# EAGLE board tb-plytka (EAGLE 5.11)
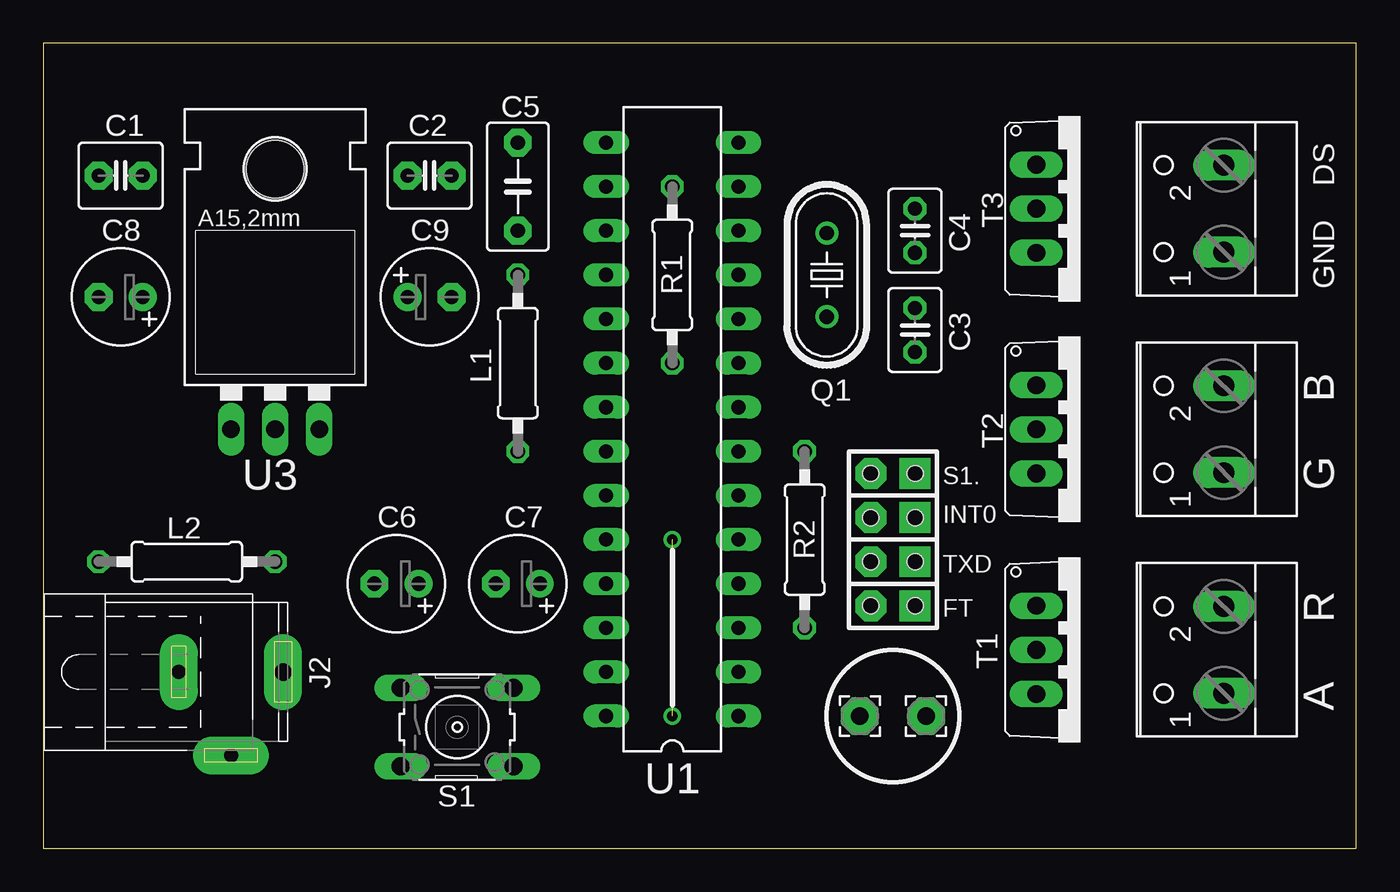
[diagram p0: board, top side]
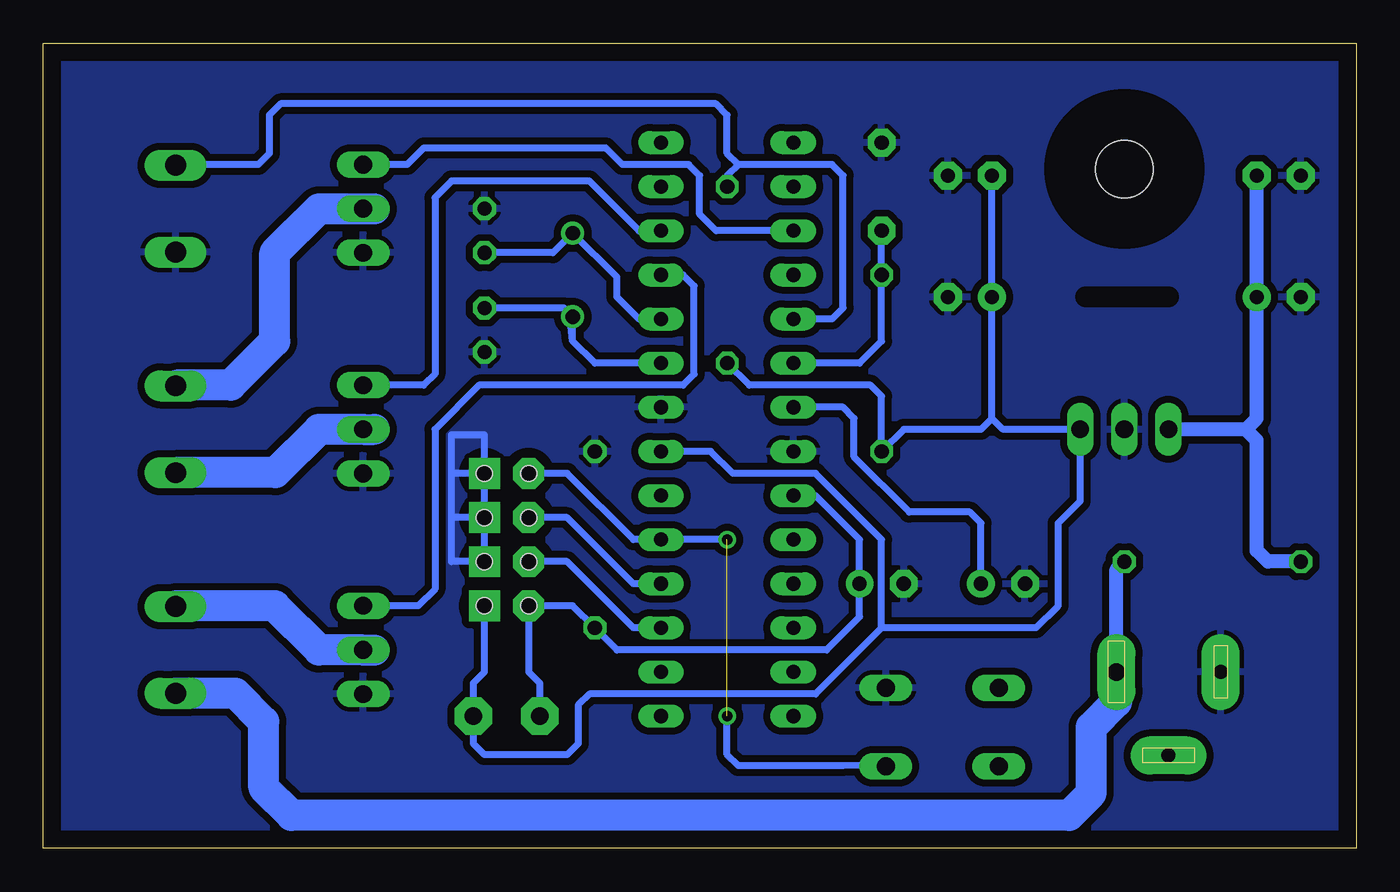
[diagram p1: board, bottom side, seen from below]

Size 75.55 x 46.34 mm. Coordinates in mm from the lower left corner, seen from the top.
Outline: 0,0 75.55,0 75.55,46.34 0,46.34 0,0
Copper layers (1*16): Top 0.035mm / dielectric 1.5mm / Bottom 0.035mm
Design rules "default": minimum track width 10mil, minimum drill 24mil, track to track 8mil, track to pad 8mil, pad to pad 8mil, via to via 8mil, smd to smd 8mil, copper to edge 40mil, drill to drill 8mil, minimum pad ring 10mil, minimum via ring 8mil, stop-mask expansion 4mil, vias tented up to drill 0mil, thermal gap 10mil
Holes 0.9 mm at 47.62,21.59 50.17,21.59 47.62,19.05 50.17,19.05 47.62,16.51 50.17,16.51 47.62,13.97 50.17,13.97
bRestrict: 1 lines

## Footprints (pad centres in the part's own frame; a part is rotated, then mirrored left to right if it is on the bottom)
C2.5-4 = drill 0.813 pad 1.6 octagon: 1 -1.27,0; 2 1.27,0
C025-030X050 = drill 0.813 octagon: 1 -1.27,0; 2 1.27,0
C5B3.5 = drill 0.813 pad 1.6 octagon: 1 -2.54,0; 2 2.54,0
E2,5-6 = drill 0.813 pad 1.6 round: + -1.27,0 | drill 0.813 pad 1.6 octagon: - 1.27,0
SIP-100-02-32 = drill 0.813 pad 1.778 square: 1 -1.27,0 | drill 0.813 pad 1.778 octagon: 2 1.27,0
SPC4077 = drill 0.8 pad 2.184 long: 1 -3,0; 2 0,-4.8 | drill 1 pad 2.184 long: 3 3,0
0207/10 = drill 0.813 octagon: 1 -5.08,0; 2 5.08,0
2,15/1,0 = drill 1.016 pad 2.159 octagon: 1 0,0
HC49U-V = drill 0.813 round: 1 -2.413,0; 2 2.413,0
B3F-10XX = drill 1.016 long: 1 -3.251,2.261; 2 3.251,2.261; 3 -3.251,-2.261; 4 3.251,-2.261
TO220V = drill 1.016 long: 1 -2.54,-2.54; 2 0,-2.54; 3 2.54,-2.54
DIL28-3 = drill 0.813 long: 1 -16.51,-3.81; 2 -13.97,-3.81; 3 -11.43,-3.81; 4 -8.89,-3.81; 5 -6.35,-3.81; 6 -3.81,-3.81; 7 -1.27,-3.81; 8 1.27,-3.81; 9 3.81,-3.81; 10 6.35,-3.81; 11 8.89,-3.81; 12 11.43,-3.81; 13 13.97,-3.81; 14 16.51,-3.81; 15 16.51,3.81; 16 13.97,3.81; 17 11.43,3.81; 18 8.89,3.81; 19 6.35,3.81; 20 3.81,3.81; 21 1.27,3.81; 22 -1.27,3.81; 23 -3.81,3.81; 24 -6.35,3.81; 25 -8.89,3.81; 26 -11.43,3.81; 27 -13.97,3.81; 28 -16.51,3.81
78XXL = drill 1.016 long: GND 0,-3.81; IN -2.54,-3.81; OUT 2.54,-3.81 | hole 3.302: 0,11.176
W237-102 = drill 1.194 long: 1 -2.5,-1.27; 2 2.5,-1.27

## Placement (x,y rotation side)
C1  100nF  [C2.5-4]  4.45,38.73 180 top
C2  100nF  [C2.5-4]  22.22,38.73 0 top
C3  22pF  [C025-030X050]  50.17,29.84 90 top
C4  22pF  [C025-030X050]  50.17,35.56 270 top
C5  100nF  [C5B3.5]  27.3,38.1 90 top
C6  1uF  [E2,5-6]  20.32,15.24 180 top
C7  47uF  [E2,5-6]  27.3,15.24 180 top
C8  220uF  [E2,5-6]  4.45,31.75 180 top
C9  100uF  [E2,5-6]  22.22,31.75 0 top
FT  2PJ  [SIP-100-02-32]  48.9,13.97 180 top
INT0  2PJ  [SIP-100-02-32]  48.9,19.05 180 top
J2  [SPC4077]  10.8,10.16 0 top
L1  10uH  [0207/10]  27.3,27.94 90 top
L2  10uH  [0207/10]  8.25,16.51 180 top
PAD5  [2,15/1,0]  50.8,7.62 270 top
PAD6  [2,15/1,0]  46.99,7.62 270 top
Q1  11,052MHz  [HC49U-V]  45.09,33.02 270 top
R1  4.7k  [0207/10]  36.2,33.02 270 top
R2  10k  [0207/10]  43.82,17.78 270 top
S1  [B3F-10XX]  23.81,6.99 0 top
S1.  2PJ  [SIP-100-02-32]  48.9,21.59 180 top
T1  BUZ11  [TO220V]  59.69,11.43 270 top
T2  BUZ11  [TO220V]  59.69,24.13 270 top
T3  BUZ11  [TO220V]  59.69,36.83 270 top
TXD  2PJ  [SIP-100-02-32]  48.9,16.51 180 top
U1  ATMEGA88-PU  [DIL28-3]  36.2,24.13 90 top
U3  7805  [78XXL]  13.34,27.94 0 top
X1  [W237-102]  66.67,11.43 90 top
X3  [W237-102]  66.67,24.13 90 top
X4  [W237-102]  66.67,36.83 90 top

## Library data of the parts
C1 C2 C5 = capacitor-wima
C3 C4 C6-C9 = rcl
FT INT0 S1. TXD = con-headers-jp
J2 = con-jack; OC_FARNELL: unknown; OC_NEWARK: unknown
L1 L2 R1 R2 = resistor
PAD5 PAD6 = wirepad
Q1 = crystal; OC_FARNELL: 1666969; OC_NEWARK: unknown
S1 = switch-omron; MPN: B3F-1000; OC_FARNELL: 176432; OC_NEWARK: 36M3542
T1-T3 = transistor
U1 = atmega8
U3 = v-reg
X1 X3 X4 = con-wago-500; MPN: 237-102; OC_FARNELL: unknown; OC_NEWARK: 70K9898

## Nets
1W: R1.1 U1.19 X4.2
+5V: C2.1 C9.+ FT.1 L1.1 PAD5.1 R1.2 U1.7 U3.OUT
+12V: J2.3 L2.1 X1.1
GND: C1.2 C2.2 C3.1 C4.1 C5.2 C6.- C7.- C8.- C9.- INT0.1 J2.1 R2.1 S1.2 S1..1 T1.3 T2.3 T3.3 TXD.1 U1.8 U1.22 U3.GND X4.1
N$4: C5.1 L1.2 U1.20
N$5: C6.+ U1.21
N$6: C7.+ FT.2 PAD6.1 R2.2 U1.23
N$7: INT0.2 U1.4
N$8: T3.2 X3.2
N$9: T2.2 X3.1
N$10: T1.2 X1.2
N$11: C1.1 C8.+ L2.2 U3.IN
N$13: T1.1 U1.11
N$14: T2.1 U1.12
N$15: TXD.2 U1.3
N$20: C3.2 Q1.2 U1.9
N$21: C4.2 Q1.1 U1.10
N$23: S1.4 S1..2 U1.5
N$24: T3.1 U1.17

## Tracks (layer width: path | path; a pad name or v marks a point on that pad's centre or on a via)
1W
  Bottom 0.406: U1.19 30.16,30.48 29.53,31.11 29.53,38.73 30.16,39.37 35.56,39.37 | R1.1 36.2,38.73 35.56,39.37 | X4.2 67.91,39.37 63.18,39.37 62.55,40 62.55,42.23 61.91,42.86 36.83,42.86 36.2,42.23 36.2,40 35.56,39.37
+5V
  Bottom 0.406: U1.7 37.15,22.86 35.88,21.59 31.11,21.59 27.3,17.78 27.3,12.7 | C2.1 C9.+ 20.95,24.77 | 27.3,12.7 31.11,8.89 44.13,8.89 44.77,8.26 44.77,6.03 45.4,5.4 50.17,5.4 50.8,6.03 PAD5.1 50.8,9.53 50.17,10.16 FT.1 | R1.2 34.93,26.67 27.94,26.67 27.3,26.04 L1.1 26.04,24.13 21.59,24.13 20.95,24.77 | 20.95,24.77 20.32,24.13 U3.OUT 15.88,20 17.14,18.73 17.14,13.97 18.41,12.7 27.3,12.7
+12V
  Bottom 0.813: J2.3 13.79,16.05 L2.1
  Bottom 1.778: J2.3 13.79,8.43 15.24,6.99 15.24,3.18 16.51,1.9 61.28,1.9 62.87,3.49 62.87,7.3 64.49,8.93 X1.1
GND
  Bottom 0.406: INT0.1 TXD.1 52.07,16.51 52.07,19.05 | INT0.1 52.07,19.05 | INT0.1 S1..1 | S1..1 50.17,23.81 52.07,23.81 52.07,21.59 | S1..1 52.07,21.59 | 52.07,19.05 52.07,21.59
  pour Bottom (isolate 0.406): -4.45,46.99 77.79,46.99 77.79,-2.54 -4.45,-2.54
N$4
  Bottom 0.406: U1.20 28.57,27.94 27.3,29.21 L1.2 C5.1
N$5
  Bottom 0.406: U1.21 29.53,25.4 28.89,24.77 28.89,22.54 25.72,19.37 22.22,19.37 21.59,18.73 C6.+
N$6
  Bottom 0.406: U1.23 31.11,20.32 28.57,17.78 C7.+ 28.57,13.34 30.48,11.43 42.55,11.43 R2.2 45.09,13.97 FT.2 47.62,10.16 46.99,9.53 PAD6.1
N$7
  Bottom 0.406: U1.4 41.59,15.24 45.4,19.05 INT0.2
N$8
  Bottom 1.778: 56.52,36.83 T3.2 59.69,36.83 62.23,34.29 62.23,29.21 64.77,26.67 67.91,26.67 X3.2
N$9
  Bottom 1.778: 56.52,24.13 T2.2 59.69,24.13 62.19,21.63 X3.1
N$10
  Bottom 1.778: 56.52,11.43 T1.2 59.69,11.43 62.23,13.97 67.91,13.97 X1.2
N$11
  Bottom 0.406: C8.+ C1.1
  Bottom 0.813: L2.2 5.08,16.51 5.72,17.14 5.72,23.5 6.35,24.13 | 6.35,24.13 U3.IN | 6.35,24.13 5.72,24.77 C8.+ C1.1
N$13
  Bottom 0.406: U1.11 38.73,33.02 38.1,32.38 38.1,27.3 38.73,26.67 50.48,26.67 53.02,24.13 53.02,14.92 53.98,13.97 T1.1
N$14
  Bottom 0.406: U1.12 41.28,35.56 44.13,38.42 52.07,38.42 53.02,37.46 53.02,27.3 53.66,26.67 T2.1
N$15
  Bottom 0.406: U1.3 41.59,12.7 45.4,16.51 TXD.2
N$20
  Bottom 0.406: U1.9 43.82,27.94 45.09,29.21 | 45.09,29.21 Q1.2 | 45.09,29.21 45.21,30.35 45.21,30.48 Q1.2 | C3.2 45.59,31.11 Q1.2
N$21
  Bottom 0.406: U1.10 41.28,30.48 42.55,31.75 42.55,32.89 Q1.1 46.23,34.29 C4.2
N$23  (via drill 0.6)  (1 unrouted)
  Bottom 0.406: v36.2,17.78 U1.5 41.59,17.78 45.4,21.59 S1..2 | v36.2,7.62 36.2,5.4 35.56,4.76 29.53,4.76 27.58,4.8 S1.4
N$24
  Bottom 0.406: U1.17 36.83,35.56 37.78,36.51 37.78,38.73 38.42,39.37 42.23,39.37 43.18,40.32 53.66,40.32 54.61,39.37 T3.1

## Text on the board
tPlace: DS | GND | B | G | R | A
